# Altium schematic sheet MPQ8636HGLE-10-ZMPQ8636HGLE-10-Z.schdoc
size 127 x 101 mm
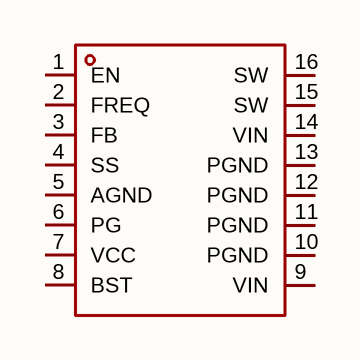
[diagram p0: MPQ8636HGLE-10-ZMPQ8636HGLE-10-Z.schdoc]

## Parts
U?  mpq8636hgle-10-z  [QFN-16_L4.0-W3.0_MPQ8636GLE-10]  (value not drawn)

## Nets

Not connected (* = marked no-connect by the designer): U? 1(EN) 2(FREQ) 3(FB) 4(SS) 5(AGND) 6(PG) 7(VCC) 8(BST) 9(VIN) 10(PGND) 11(PGND) 12(PGND) 13(PGND) 14(VIN) 15(SW) 16(SW)

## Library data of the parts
U? = mpq8636hgle-10-z: 功能类型:降压型;工作电压:4.5V~18V;输出电压:611mV~13V;输出电流:10A;输出类型:可调;; Manufacturer: MPS(芯源); AddInBom: yes; ModelId: e4a32ea304a14330920ee9e4ec08a665; ModelTransform: 118.5037,158.267,0,0,0,0,6.85,0,0; Function: 降压型; Output Current: 10A; Frequency - Switching: 200kHz~1MHz; Synchronous Rectifier: 是; Number of Outputs: 1; Topology: 降压式; Quiescent Current: 860uA; Switch tube (built-in/external): 内置; Output Type: 可调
